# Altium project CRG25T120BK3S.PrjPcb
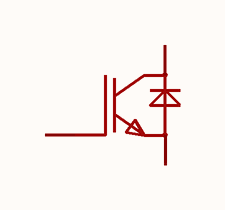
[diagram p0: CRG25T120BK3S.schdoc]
1 sheet, 1 parts. Net scope: global (net labels, ports and power ports of the same name join across sheets).

## Sheet CRG25T120BK3S.schdoc
size 127 x 101 mm

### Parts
U?  crg25t120bk3s  [TO-247-3_L15.8-W5.0-P5.44-L]  (value not drawn)

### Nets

Not connected (* = marked no-connect by the designer): U? 1(G) 2(C) 3(E)

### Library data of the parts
U? = crg25t120bk3s: IGBT类型:-;耗散功率(Pd):278W;集射极击穿电压(Vces):1.2kV;集电极电流(Ic):25A;; Manufacturer: CRMICRO(华润微); AddInBom: yes; ModelId: 2dc33f6e48bd44aa838c2b9e2b85eb16; ModelTransform: 622.04631,185.078,0,0,0,0,-0.003,13.778,-196.85; Pd - Power Dissipation: 278W; Collector-Emitter Breakdown Voltage (Vces): 1.2kV; Current - Collector(Ic): 25A; Current - Collector Pulsed (Icm): 75A; Vce Saturation(VCE(sat)): 2.5V@25A,15V; Gate-Emitter Threshold Voltage (Vge(th)@Ic): 4.5V@250uA; Gate Charge(Qg): 141.2nC@15V; Input Capacitance(Cies): 1.914nF; Output Capacitance(Coes): 77pF; Reverse Transfer Capacitance (Cres): 40pF; Td(on): 48ns; Td(off): 200ns; Turn-On Energy (Eon): 2.7mJ; Switching Energy(Eoff): 800uJ; Reverse Recovery Time(trr): 80ns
